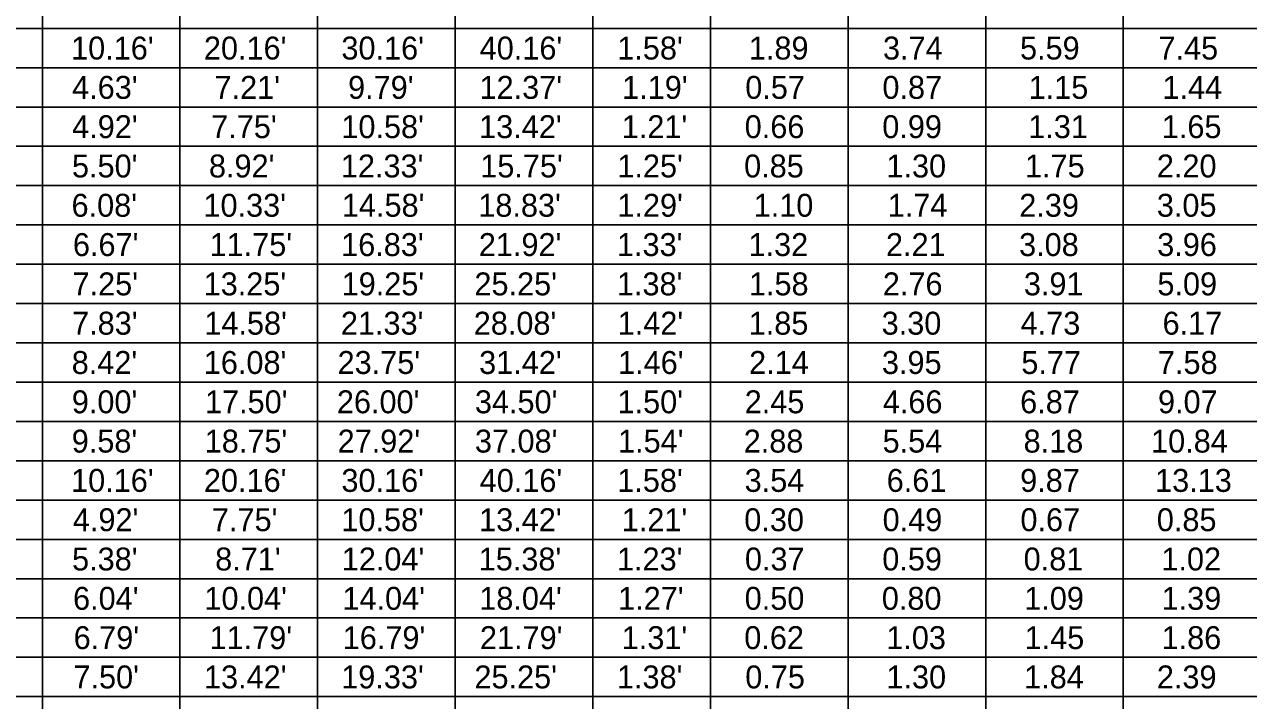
# Model space of a CAD drawing. Extents: x 1.7 to 14.6, y 0 to 8.4.
# Drawn here: x 6.325 to 10.062, y 4.218 to 6.282 of the extents above; entities that cross this region are included whole.
import ezdxf

# ---------------------------------------------------------------- set-up
doc = ezdxf.new("R2010")
doc.units = 0
doc.layers.add('Table', color=7, linetype='Continuous')

msp = doc.modelspace()

# ---------------------------------------------------------------- linework, layer by layer
at = {"layer": 'Table'}
for points in [[(6.38, 6.39), (6.38, 6.27), (6.38, 6.15), (6.38, 6.03), (6.38, 5.91), (6.38, 5.79), (6.38, 5.67), (6.38, 5.55), (6.38, 5.43), (6.38, 5.31), (6.38, 5.19), (6.38, 5.07), (6.38, 4.95), (6.38, 4.83), (6.38, 4.71), (6.38, 4.59), (6.38, 4.47), (6.38, 4.35), (6.38, 4.23), (6.38, 4.11)], [(6.8, 6.39), (6.8, 6.27), (6.8, 6.15), (6.8, 6.03), (6.8, 5.91), (6.8, 5.79), (6.8, 5.67), (6.8, 5.55), (6.8, 5.43), (6.8, 5.31), (6.8, 5.19), (6.8, 5.07), (6.8, 4.95), (6.8, 4.83), (6.8, 4.71), (6.8, 4.59), (6.8, 4.47), (6.8, 4.35), (6.8, 4.23), (6.8, 4.11)], [(7.22, 6.39), (7.22, 6.27), (7.22, 6.15), (7.22, 6.03), (7.22, 5.91), (7.22, 5.79), (7.22, 5.67), (7.22, 5.55), (7.22, 5.43), (7.22, 5.31), (7.22, 5.19), (7.22, 5.07), (7.22, 4.95), (7.22, 4.83), (7.22, 4.71), (7.22, 4.59), (7.22, 4.47), (7.22, 4.35), (7.22, 4.23), (7.22, 4.11)], [(7.64, 6.39), (7.64, 6.27), (7.64, 6.15), (7.64, 6.03), (7.64, 5.91), (7.64, 5.79), (7.64, 5.67), (7.64, 5.55), (7.64, 5.43), (7.64, 5.31), (7.64, 5.19), (7.64, 5.07), (7.64, 4.95), (7.64, 4.83), (7.64, 4.71), (7.64, 4.59), (7.64, 4.47), (7.64, 4.35), (7.64, 4.23), (7.64, 4.11)], [(8.06, 6.39), (8.06, 6.27), (8.06, 6.15), (8.06, 6.03), (8.06, 5.91), (8.06, 5.79), (8.06, 5.67), (8.06, 5.55), (8.06, 5.43), (8.06, 5.31), (8.06, 5.19), (8.06, 5.07), (8.06, 4.95), (8.06, 4.83), (8.06, 4.71), (8.06, 4.59), (8.06, 4.47), (8.06, 4.35), (8.06, 4.23), (8.06, 4.11)], [(8.42, 6.39), (8.42, 6.27), (8.42, 6.15), (8.42, 6.03), (8.42, 5.91), (8.42, 5.79), (8.42, 5.67), (8.42, 5.55), (8.42, 5.43), (8.42, 5.31), (8.42, 5.19), (8.42, 5.07), (8.42, 4.95), (8.42, 4.83), (8.42, 4.71), (8.42, 4.59), (8.42, 4.47), (8.42, 4.35), (8.42, 4.23), (8.42, 4.11)], [(8.84, 6.39), (8.84, 6.27), (8.84, 6.15), (8.84, 6.03), (8.84, 5.91), (8.84, 5.79), (8.84, 5.67), (8.84, 5.55), (8.84, 5.43), (8.84, 5.31), (8.84, 5.19), (8.84, 5.07), (8.84, 4.95), (8.84, 4.83), (8.84, 4.71), (8.84, 4.59), (8.84, 4.47), (8.84, 4.35), (8.84, 4.23), (8.84, 4.11)], [(9.26, 6.39), (9.26, 6.27), (9.26, 6.15), (9.26, 6.03), (9.26, 5.91), (9.26, 5.79), (9.26, 5.67), (9.26, 5.55), (9.26, 5.43), (9.26, 5.31), (9.26, 5.19), (9.26, 5.07), (9.26, 4.95), (9.26, 4.83), (9.26, 4.71), (9.26, 4.59), (9.26, 4.47), (9.26, 4.35), (9.26, 4.23), (9.26, 4.11)], [(9.68, 6.39), (9.68, 6.27), (9.68, 6.15), (9.68, 6.03), (9.68, 5.91), (9.68, 5.79), (9.68, 5.67), (9.68, 5.55), (9.68, 5.43), (9.68, 5.31), (9.68, 5.19), (9.68, 5.07), (9.68, 4.95), (9.68, 4.83), (9.68, 4.71), (9.68, 4.59), (9.68, 4.47), (9.68, 4.35), (9.68, 4.23), (9.68, 4.11)], [(6.02, 6.27), (6.38, 6.27), (6.8, 6.27), (7.22, 6.27), (7.64, 6.27), (8.06, 6.27), (8.42, 6.27), (8.84, 6.27), (9.26, 6.27), (9.68, 6.27), (10.1, 6.27), (10.52, 6.27), (10.94, 6.27), (11.36, 6.27), (11.78, 6.27), (12.2, 6.27), (12.62, 6.27), (13.04, 6.27), (13.46, 6.27)], [(6.02, 6.15), (6.38, 6.15), (6.8, 6.15), (7.22, 6.15), (7.64, 6.15), (8.06, 6.15), (8.42, 6.15), (8.84, 6.15), (9.26, 6.15), (9.68, 6.15), (10.1, 6.15), (10.52, 6.15), (10.94, 6.15), (11.36, 6.15), (11.78, 6.15), (12.2, 6.15), (12.62, 6.15), (13.04, 6.15), (13.46, 6.15)], [(6.02, 6.03), (6.38, 6.03), (6.8, 6.03), (7.22, 6.03), (7.64, 6.03), (8.06, 6.03), (8.42, 6.03), (8.84, 6.03), (9.26, 6.03), (9.68, 6.03), (10.1, 6.03), (10.52, 6.03), (10.94, 6.03), (11.36, 6.03), (11.78, 6.03), (12.2, 6.03), (12.62, 6.03), (13.04, 6.03), (13.46, 6.03)], [(6.02, 5.91), (6.38, 5.91), (6.8, 5.91), (7.22, 5.91), (7.64, 5.91), (8.06, 5.91), (8.42, 5.91), (8.84, 5.91), (9.26, 5.91), (9.68, 5.91), (10.1, 5.91), (10.52, 5.91), (10.94, 5.91), (11.36, 5.91), (11.78, 5.91), (12.2, 5.91), (12.62, 5.91), (13.04, 5.91), (13.46, 5.91)], [(6.02, 5.79), (6.38, 5.79), (6.8, 5.79), (7.22, 5.79), (7.64, 5.79), (8.06, 5.79), (8.42, 5.79), (8.84, 5.79), (9.26, 5.79), (9.68, 5.79), (10.1, 5.79), (10.52, 5.79), (10.94, 5.79), (11.36, 5.79), (11.78, 5.79), (12.2, 5.79), (12.62, 5.79), (13.04, 5.79), (13.46, 5.79)], [(6.02, 5.67), (6.38, 5.67), (6.8, 5.67), (7.22, 5.67), (7.64, 5.67), (8.06, 5.67), (8.42, 5.67), (8.84, 5.67), (9.26, 5.67), (9.68, 5.67), (10.1, 5.67), (10.52, 5.67), (10.94, 5.67), (11.36, 5.67), (11.78, 5.67), (12.2, 5.67), (12.62, 5.67), (13.04, 5.67), (13.46, 5.67)], [(6.02, 5.55), (6.38, 5.55), (6.8, 5.55), (7.22, 5.55), (7.64, 5.55), (8.06, 5.55), (8.42, 5.55), (8.84, 5.55), (9.26, 5.55), (9.68, 5.55), (10.1, 5.55), (10.52, 5.55), (10.94, 5.55), (11.36, 5.55), (11.78, 5.55), (12.2, 5.55), (12.62, 5.55), (13.04, 5.55), (13.46, 5.55)], [(6.02, 5.43), (6.38, 5.43), (6.8, 5.43), (7.22, 5.43), (7.64, 5.43), (8.06, 5.43), (8.42, 5.43), (8.84, 5.43), (9.26, 5.43), (9.68, 5.43), (10.1, 5.43), (10.52, 5.43), (10.94, 5.43), (11.36, 5.43), (11.78, 5.43), (12.2, 5.43), (12.62, 5.43), (13.04, 5.43), (13.46, 5.43)], [(6.02, 5.31), (6.38, 5.31), (6.8, 5.31), (7.22, 5.31), (7.64, 5.31), (8.06, 5.31), (8.42, 5.31), (8.84, 5.31), (9.26, 5.31), (9.68, 5.31), (10.1, 5.31), (10.52, 5.31), (10.94, 5.31), (11.36, 5.31), (11.78, 5.31), (12.2, 5.31), (12.62, 5.31), (13.04, 5.31), (13.46, 5.31)], [(6.02, 5.19), (6.38, 5.19), (6.8, 5.19), (7.22, 5.19), (7.64, 5.19), (8.06, 5.19), (8.42, 5.19), (8.84, 5.19), (9.26, 5.19), (9.68, 5.19), (10.1, 5.19), (10.52, 5.19), (10.94, 5.19), (11.36, 5.19), (11.78, 5.19), (12.2, 5.19), (12.62, 5.19), (13.04, 5.19), (13.46, 5.19)], [(6.02, 5.07), (6.38, 5.07), (6.8, 5.07), (7.22, 5.07), (7.64, 5.07), (8.06, 5.07), (8.42, 5.07), (8.84, 5.07), (9.26, 5.07), (9.68, 5.07), (10.1, 5.07), (10.52, 5.07), (10.94, 5.07), (11.36, 5.07), (11.78, 5.07), (12.2, 5.07), (12.62, 5.07), (13.04, 5.07), (13.46, 5.07)], [(6.02, 4.95), (6.38, 4.95), (6.8, 4.95), (7.22, 4.95), (7.64, 4.95), (8.06, 4.95), (8.42, 4.95), (8.84, 4.95), (9.26, 4.95), (9.68, 4.95), (10.1, 4.95), (10.52, 4.95), (10.94, 4.95), (11.36, 4.95), (11.78, 4.95), (12.2, 4.95), (12.62, 4.95), (13.04, 4.95), (13.46, 4.95)], [(6.02, 4.83), (6.38, 4.83), (6.8, 4.83), (7.22, 4.83), (7.64, 4.83), (8.06, 4.83), (8.42, 4.83), (8.84, 4.83), (9.26, 4.83), (9.68, 4.83), (10.1, 4.83), (10.52, 4.83), (10.94, 4.83), (11.36, 4.83), (11.78, 4.83), (12.2, 4.83), (12.62, 4.83), (13.04, 4.83), (13.46, 4.83)], [(6.02, 4.71), (6.38, 4.71), (6.8, 4.71), (7.22, 4.71), (7.64, 4.71), (8.06, 4.71), (8.42, 4.71), (8.84, 4.71), (9.26, 4.71), (9.68, 4.71), (10.1, 4.71), (10.52, 4.71), (10.94, 4.71), (11.36, 4.71), (11.78, 4.71), (12.2, 4.71), (12.62, 4.71), (13.04, 4.71), (13.46, 4.71)], [(6.02, 4.59), (6.38, 4.59), (6.8, 4.59), (7.22, 4.59), (7.64, 4.59), (8.06, 4.59), (8.42, 4.59), (8.84, 4.59), (9.26, 4.59), (9.68, 4.59), (10.1, 4.59), (10.52, 4.59), (10.94, 4.59), (11.36, 4.59), (11.78, 4.59), (12.2, 4.59), (12.62, 4.59), (13.04, 4.59), (13.46, 4.59)], [(6.02, 4.47), (6.38, 4.47), (6.8, 4.47), (7.22, 4.47), (7.64, 4.47), (8.06, 4.47), (8.42, 4.47), (8.84, 4.47), (9.26, 4.47), (9.68, 4.47), (10.1, 4.47), (10.52, 4.47), (10.94, 4.47), (11.36, 4.47), (11.78, 4.47), (12.2, 4.47), (12.62, 4.47), (13.04, 4.47), (13.46, 4.47)], [(6.02, 4.35), (6.38, 4.35), (6.8, 4.35), (7.22, 4.35), (7.64, 4.35), (8.06, 4.35), (8.42, 4.35), (8.84, 4.35), (9.26, 4.35), (9.68, 4.35), (10.1, 4.35), (10.52, 4.35), (10.94, 4.35), (11.36, 4.35), (11.78, 4.35), (12.2, 4.35), (12.62, 4.35), (13.04, 4.35), (13.46, 4.35)], [(6.02, 4.23), (6.38, 4.23), (6.8, 4.23), (7.22, 4.23), (7.64, 4.23), (8.06, 4.23), (8.42, 4.23), (8.84, 4.23), (9.26, 4.23), (9.68, 4.23), (10.1, 4.23), (10.52, 4.23), (10.94, 4.23), (11.36, 4.23), (11.78, 4.23), (12.2, 4.23), (12.62, 4.23), (13.04, 4.23), (13.46, 4.23)]]:
    msp.add_lwpolyline(points, dxfattribs=at)

# ---------------------------------------------------------------- texts
for s, p in [("10.16'", (6.4675, 6.175)), ("20.16'", (6.873, 6.175)), ("30.16'", (7.2929, 6.175)), ("40.16'", (7.715, 6.175)), ("1.58'", (8.1351, 6.175)), ('1.89', (8.5369, 6.175)), ('3.74', (8.9463, 6.175)), ('5.59', (9.3647, 6.175)), ('7.45', (9.7875, 6.175)), (" 4.63'", (6.4446, 6.055)), (" 7.21'", (6.8794, 6.055)), (" 9.79'", (7.2871, 6.055)), ("12.37'", (7.7146, 6.055)), ("1.19'", (8.1499, 6.055)), ('0.57', (8.5259, 6.055)), ('0.87', (8.9446, 6.055)), ('1.15', (9.3911, 6.055)), ('1.44', (9.7997, 6.055)), (" 4.92'", (6.4447, 5.935)), (" 7.75'", (6.8693, 5.935)), ("10.58'", (7.2927, 5.935)), ("13.42'", (7.7133, 5.935)), ("1.21'", (8.1488, 5.935)), ('0.66', (8.5242, 5.935)), ('0.99', (8.9442, 5.935)), ('1.31', (9.3899, 5.935)), ('1.65', (9.7977, 5.935)), (" 5.50'", (6.4442, 5.815)), (" 8.92'", (6.8624, 5.815)), ("12.33'", (7.2912, 5.815)), ("15.75'", (7.7168, 5.815)), ("1.25'", (8.1354, 5.815)), ('0.85', (8.5224, 5.815)), ('1.30', (8.9569, 5.815)), ('1.75', (9.3799, 5.815)), ('2.20', (9.7825, 5.815)), (" 6.08'", (6.4429, 5.695)), ("10.33'", (6.8717, 5.695)), ("14.58'", (7.2943, 5.695)), ("18.83'", (7.7108, 5.695)), ("1.29'", (8.1354, 5.695)), ('1.10', (8.5515, 5.695)), ('1.74', (8.9609, 5.695)), ('2.39', (9.3625, 5.695)), ('3.05', (9.7825, 5.695)), (" 6.67'", (6.4471, 5.575)), ("11.75'", (6.8903, 5.575)), ("16.83'", (7.2921, 5.575)), ("21.92'", (7.7124, 5.575)), ("1.33'", (8.1341, 5.575)), ('1.32', (8.5358, 5.575)), ('2.21', (8.9555, 5.575)), ('3.08', (9.3619, 5.575)), ('3.96', (9.7836, 5.575)), (" 7.25'", (6.4459, 5.455)), ("13.25'", (6.8723, 5.455)), ("19.25'", (7.2935, 5.455)), ("25.25'", (7.699, 5.455)), ("1.38'", (8.134, 5.455)), ('1.58', (8.537, 5.455)), ('2.76', (8.9459, 5.455)), ('3.91', (9.3765, 5.455)), ('5.09', (9.7842, 5.455)), (" 7.83'", (6.4446, 5.335)), ("14.58'", (6.8743, 5.335)), ("21.33'", (7.2912, 5.335)), ("28.08'", (7.6969, 5.335)), ("1.42'", (8.1364, 5.335)), ('1.85', (8.5364, 5.335)), ('3.30', (8.9423, 5.335)), ('4.73', (9.3666, 5.335)), ('6.17', (9.8, 5.335)), (" 8.42'", (6.4434, 5.215)), ("16.08'", (6.8727, 5.215)), ("23.75'", (7.2812, 5.215)), ("31.42'", (7.7133, 5.215)), ("1.46'", (8.1375, 5.215)), ('2.14', (8.5376, 5.215)), ('3.95', (8.9431, 5.215)), ('5.77', (9.3688, 5.215)), ('7.58', (9.7858, 5.215)), (" 9.00'", (6.4437, 5.095)), ("17.50'", (6.8763, 5.095)), ("26.00'", (7.279, 5.095)), ("34.50'", (7.7004, 5.095)), ("1.50'", (8.1359, 5.095)), ('2.45', (8.5242, 5.095)), ('4.66', (8.9458, 5.095)), ('6.87', (9.3652, 5.095)), ('9.07', (9.786, 5.095)), (" 9.58'", (6.4435, 4.975)), ("18.75'", (6.8755, 4.975)), ("27.92'", (7.2813, 4.975)), ("37.08'", (7.7004, 4.975)), ('2.88', (8.5212, 4.975)), ('8.18', (9.3757, 4.975)), ('10.84', (9.7649, 4.975)), ("1.54'", (8.1374, 4.975)), ('5.54', (8.9452, 4.975)), ("10.16'", (6.4675, 4.855)), ("20.16'", (6.873, 4.855)), ("30.16'", (7.2929, 4.855)), ("40.16'", (7.715, 4.855)), ("1.58'", (8.1351, 4.855)), ('3.54', (8.524, 4.855)), ('6.61', (8.9577, 4.855)), ('9.87', (9.3652, 4.855)), ('13.13', (9.7772, 4.855)), ("4.92'", (6.4729, 4.735)), ("7.75'", (6.8975, 4.735)), ("10.58'", (7.2927, 4.735)), ("13.42'", (7.7133, 4.735)), ("1.21'", (8.1488, 4.735)), ('0.30', (8.5229, 4.735)), ('0.49', (8.9452, 4.735)), ('0.67', (9.366, 4.735)), ('0.85', (9.7824, 4.735)), ("5.38'", (6.4705, 4.615)), ("8.71'", (6.9074, 4.615)), ("12.04'", (7.2939, 4.615)), ("15.38'", (7.7121, 4.615)), ("1.23'", (8.1342, 4.615)), ('0.37', (8.5248, 4.615)), ('0.59', (8.9442, 4.615)), ('0.81', (9.3758, 4.615)), ('1.02', (9.7964, 4.615)), ("6.04'", (6.4735, 4.495)), ("10.04'", (6.8745, 4.495)), ("14.04'", (7.296, 4.495)), ("18.04'", (7.7137, 4.495)), ("1.27'", (8.1376, 4.495)), ('0.50', (8.5241, 4.495)), ('0.80', (8.9428, 4.495)), ('1.09', (9.3776, 4.495)), ('1.39', (9.797, 4.495)), ("6.79'", (6.4753, 4.375)), ("11.79'", (6.8903, 4.375)), ("16.79'", (7.2969, 4.375)), ("21.79'", (7.7158, 4.375)), ("1.31'", (8.1487, 4.375)), ('0.62', (8.5229, 4.375)), ('1.03', (8.9563, 4.375)), ('1.45', (9.3787, 4.375)), ('1.86', (9.7969, 4.375)), ("7.50'", (6.4747, 4.255)), ("13.42'", (6.8733, 4.255)), ("19.33'", (7.2923, 4.255)), ("25.25'", (7.699, 4.255)), ("1.38'", (8.134, 4.255)), ('0.75', (8.5259, 4.255)), ('1.30', (8.9569, 4.255)), ('1.84', (9.3774, 4.255)), ('2.39', (9.7825, 4.255))]:
    msp.add_text(s, height=0.07, rotation=0, dxfattribs=at).set_placement(p)

doc.saveas('drawing.dxf')
